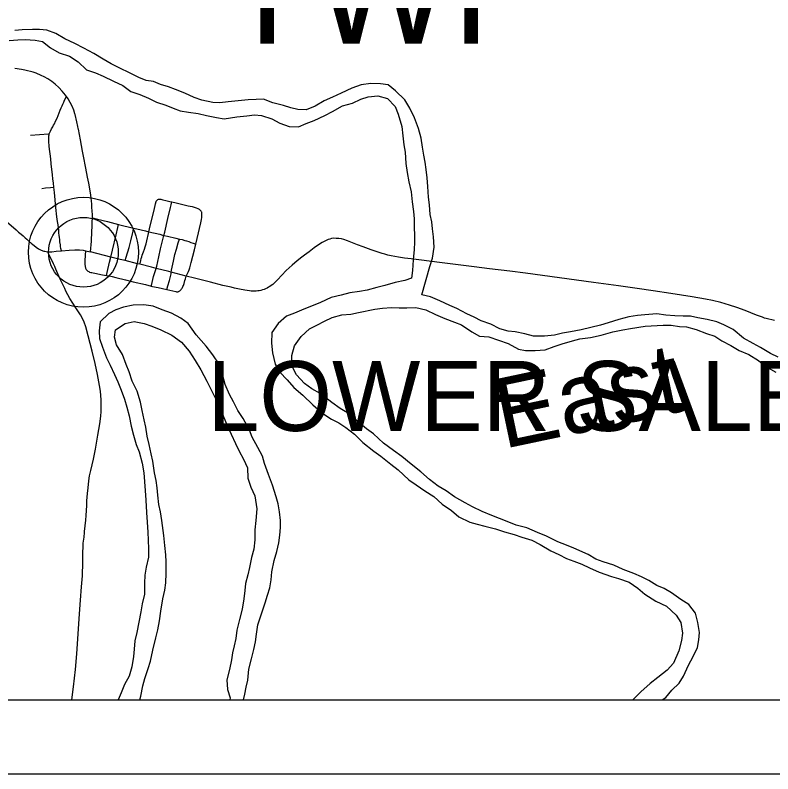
# Model space of a CAD drawing. Extents: x 0 to 34, y 0 to 22.
# Drawn here: x 3.105 to 4.132, y 14 to 15.027 of the extents above; entities that cross this region are included whole.
import ezdxf

# ---------------------------------------------------------------- set-up
doc = ezdxf.new("R2010")
doc.units = 0
for name, color, linetype in [('GM_X_Corporation', 7, 'Continuous'), ('GM_X_Corporation_Text', 7, 'Continuous'), ('GM_X_Major_River', 7, 'Continuous'), ('GM_X_Major_River_Text', 7, 'Continuous'), ('GM_X_State_Route', 7, 'Continuous'), ('GM_X_Township_Road', 7, 'Continuous'), ('GM_X_Township_Text', 7, 'Continuous'), ('GM_X_Unincorporated', 7, 'Continuous'), ('GM_X_Unincorporated_Location', 7, 'Continuous'), ('SH_Data', 7, 'Continuous'), ('SH_Text', 7, 'Continuous')]:
    doc.layers.add(name, color=color, linetype=linetype)

msp = doc.modelspace()

# ---------------------------------------------------------------- linework, layer by layer
at = {"layer": 'GM_X_Corporation'}
msp.add_lwpolyline([(2.1, 19.4241), (2.1, 14.1), (8.9, 14.1), (8.9, 16.8499)], dxfattribs=at)
at = {"layer": 'GM_X_Major_River'}
for points in [[(3.6559, 14.6484), (3.6671, 14.6869), (3.6704, 14.6983), (3.6728, 14.7128), (3.6719, 14.7272), (3.6706, 14.7378), (3.6697, 14.7473), (3.6673, 14.7571), (3.6664, 14.7704), (3.6651, 14.7806), (3.6641, 14.795), (3.6632, 14.8071), (3.6619, 14.8181), (3.6607, 14.828), (3.659, 14.8378), (3.657, 14.8484), (3.6553, 14.8605), (3.6517, 14.8737), (3.6462, 14.8881), (3.64, 14.9013), (3.633, 14.9126), (3.6203, 14.9249), (3.6104, 14.9328), (3.6001, 14.9341), (3.5872, 14.9347), (3.5739, 14.933), (3.5611, 14.9283), (3.5468, 14.9216), (3.5351, 14.9162), (3.5238, 14.9111), (3.5118, 14.9041), (3.4993, 14.899), (3.4883, 14.8992), (3.4785, 14.9017), (3.4689, 14.9047), (3.4545, 14.9086), (3.4415, 14.9134), (3.4317, 14.9129), (3.4211, 14.9127), (3.4074, 14.911), (3.3938, 14.9097), (3.3824, 14.9084), (3.373, 14.909), (3.3581, 14.9119), (3.3478, 14.9155), (3.3353, 14.9214), (3.3223, 14.9266), (3.3128, 14.9302), (3.3021, 14.9331), (3.2926, 14.9372), (3.2827, 14.9386), (3.2728, 14.9426), (3.2594, 14.9496), (3.248, 14.9548), (3.2354, 14.9611), (3.2247, 14.9674), (3.2117, 14.9752), (3.1983, 14.9826), (3.1861, 14.9888), (3.1724, 14.9951), (3.1605, 15.0025), (3.1483, 15.0069), (3.1385, 15.0076), (3.1286, 15.0078), (3.115, 15.0072), (3.1047, 15.0063)], [(3.097, 14.993), (3.1091, 14.9939), (3.1189, 14.9944), (3.1322, 14.9931), (3.1425, 14.9913), (3.1532, 14.9831), (3.1651, 14.976), (3.1788, 14.9717), (3.1906, 14.9639), (3.2021, 14.953), (3.2143, 14.949), (3.2246, 14.9446), (3.2384, 14.9376), (3.2513, 14.9317), (3.2621, 14.9239), (3.2742, 14.9199), (3.2861, 14.9147), (3.2967, 14.9095), (3.3093, 14.9055), (3.3192, 14.9011), (3.3287, 14.8978), (3.3402, 14.8957), (3.3531, 14.894), (3.3645, 14.8915), (3.3778, 14.8886), (3.3884, 14.8869), (3.4054, 14.8894), (3.4191, 14.8907), (3.4293, 14.892), (3.4388, 14.8913), (3.4529, 14.8866), (3.4636, 14.8811), (3.4765, 14.8763), (3.489, 14.8761), (3.4996, 14.8804), (3.5105, 14.8847), (3.5248, 14.8914), (3.535, 14.8968), (3.5486, 14.9042), (3.5622, 14.9082), (3.5735, 14.9133), (3.5833, 14.9164), (3.5965, 14.9178), (3.6095, 14.9141), (3.6202, 14.9033), (3.6242, 14.8931), (3.6289, 14.8765), (3.6306, 14.8636), (3.6319, 14.8515), (3.6336, 14.8416), (3.6345, 14.8261), (3.6362, 14.8143), (3.6387, 14.8015), (3.6419, 14.7879), (3.6432, 14.7742), (3.6449, 14.7613), (3.6458, 14.7515), (3.6456, 14.739), (3.6461, 14.7295), (3.6462, 14.72), (3.6456, 14.7097), (3.6446, 14.6957), (3.6437, 14.6813), (3.6423, 14.671), (3.6329, 14.6678)], [(3.6329, 14.6678), (3.62, 14.665), (3.6061, 14.661), (3.5951, 14.6586), (3.5819, 14.6546), (3.5717, 14.653), (3.5584, 14.6513), (3.5467, 14.6481), (3.5335, 14.6449), (3.5188, 14.6382), (3.5067, 14.6331), (3.4965, 14.6292), (3.4837, 14.6237), (3.4728, 14.6194), (3.4615, 14.6097)], [(3.8719, 14.6012), (3.8575, 14.5984), (3.8465, 14.5964), (3.8359, 14.5939), (3.8223, 14.5926), (3.8072, 14.5924), (3.7957, 14.5957), (3.7824, 14.5985), (3.7729, 14.5995), (3.7619, 14.6024), (3.7497, 14.6087), (3.7364, 14.6135), (3.7268, 14.6183), (3.7169, 14.6227), (3.7035, 14.6301), (3.694, 14.6341), (3.6806, 14.6404), (3.6677, 14.6459), (3.6559, 14.6484)], [(3.4146, 14.1), (3.4164, 14.1079), (3.4181, 14.1174), (3.4203, 14.1269), (3.422, 14.1418), (3.4252, 14.1558), (3.4284, 14.1684), (3.431, 14.1787), (3.4323, 14.189), (3.4341, 14.2015), (3.4384, 14.2152), (3.4439, 14.2316), (3.4472, 14.2419), (3.4501, 14.2518), (3.4522, 14.2624), (3.4528, 14.2735), (3.456, 14.2887), (3.4596, 14.3009), (3.4625, 14.3127), (3.4639, 14.3229), (3.4649, 14.3336), (3.4648, 14.3431), (3.4635, 14.3548), (3.4614, 14.3654), (3.459, 14.3752), (3.4539, 14.3907), (3.4484, 14.4051), (3.4432, 14.4202), (3.4401, 14.43), (3.4339, 14.442), (3.4265, 14.4556), (3.4225, 14.4654), (3.414, 14.4809), (3.407, 14.4921), (3.4012, 14.5034), (3.3954, 14.5136), (3.3899, 14.5272), (3.3859, 14.5423), (3.3815, 14.5544), (3.373, 14.5672), (3.3641, 14.5792), (3.3507, 14.5942), (3.3395, 14.6096), (3.3295, 14.6167), (3.3169, 14.6237), (3.3043, 14.6281), (3.2921, 14.6333), (3.2796, 14.635), (3.2652, 14.6344), (3.252, 14.6316), (3.2418, 14.6284), (3.232, 14.623), (3.2204, 14.6118), (3.219, 14.5996), (3.2196, 14.5894), (3.2235, 14.5777), (3.229, 14.563), (3.2341, 14.5532), (3.2399, 14.5404), (3.2442, 14.5305), (3.2489, 14.5196), (3.2533, 14.5071), (3.2565, 14.4962), (3.2596, 14.4845), (3.2625, 14.4705), (3.2657, 14.4587), (3.2693, 14.4459), (3.2732, 14.4357), (3.2772, 14.4206), (3.2796, 14.4077), (3.2815, 14.3835), (3.2824, 14.3706), (3.2834, 14.3539), (3.2843, 14.3406), (3.2849, 14.3273), (3.2854, 14.3164), (3.286, 14.3046), (3.2857, 14.2932)], [(3.9815, 14.1), (3.9866, 14.1035), (3.9948, 14.1134), (4.0046, 14.1227), (4.0105, 14.1322), (4.0175, 14.1471), (4.0238, 14.1586), (4.0297, 14.1712), (4.0311, 14.1815), (4.0321, 14.1913), (4.03, 14.205), (4.0268, 14.2175), (4.0179, 14.2291), (4.0068, 14.2358), (3.9942, 14.2451), (3.9843, 14.2507), (3.9743, 14.2551), (3.9636, 14.2618), (3.9537, 14.2666), (3.9434, 14.271), (3.9289, 14.2768), (3.916, 14.2824), (3.9015, 14.2871), (3.8916, 14.2908), (3.8813, 14.2967), (3.8622, 14.3055), (3.8519, 14.3096), (3.8401, 14.314), (3.8248, 14.3217), (3.8126, 14.3265), (3.7985, 14.3328), (3.7841, 14.3367), (3.7719, 14.3415), (3.7612, 14.3455), (3.7509, 14.3499), (3.7379, 14.3551), (3.7246, 14.3614), (3.7147, 14.3669), (3.7005, 14.3751), (3.689, 14.3833), (3.6783, 14.3896), (3.6665, 14.3985), (3.6546, 14.409), (3.6419, 14.419), (3.6289, 14.4295), (3.6178, 14.4377), (3.6044, 14.4478), (3.5906, 14.4601), (3.581, 14.4672), (3.5706, 14.4758), (3.5599, 14.4862), (3.5457, 14.4944), (3.5343, 14.5026), (3.5182, 14.5149), (3.5071, 14.5212), (3.4971, 14.5286), (3.4864, 14.5403), (3.4801, 14.5523), (3.4799, 14.5664), (3.4836, 14.5793), (3.4929, 14.592), (3.5041, 14.6023), (3.5139, 14.6074), (3.5241, 14.6129), (3.5346, 14.6176), (3.5478, 14.6212), (3.5599, 14.6225), (3.5705, 14.6245), (3.5924, 14.6293), (3.6027, 14.6306), (3.6152, 14.6315), (3.6254, 14.6309), (3.6357, 14.6307), (3.6478, 14.6312), (3.6615, 14.628), (3.6748, 14.6217), (3.6874, 14.6166), (3.7004, 14.6115), (3.7099, 14.6078), (3.7237, 14.5985), (3.7344, 14.5926), (3.7469, 14.5916), (3.7598, 14.5872), (3.7732, 14.5825), (3.7869, 14.5747), (3.7964, 14.5733), (3.8097, 14.5731), (3.8233, 14.574), (3.8354, 14.5787), (3.846, 14.5823), (3.8603, 14.5863), (3.8701, 14.5887), (3.8845, 14.5908), (3.8989, 14.594), (3.9147, 14.5984), (3.9284, 14.6009), (3.9389, 14.6029)], [(4.1389, 14.5639), (4.1282, 14.569), (4.1148, 14.5772), (4.1049, 14.5828), (4.0919, 14.5898), (4.0777, 14.6014), (4.0651, 14.608), (4.0556, 14.6121), (4.0427, 14.6153), (4.0301, 14.6174), (4.0202, 14.6196), (4.01, 14.6198), (3.999, 14.62), (3.9865, 14.621), (3.9743, 14.6227), (3.958, 14.6214), (3.9482, 14.6205), (3.9365, 14.6188), (3.9229, 14.6152), (3.9085, 14.6105), (3.8979, 14.6073), (3.8851, 14.6041), (3.8719, 14.6012)], [(3.2742, 14.1), (3.2754, 14.1053), (3.2782, 14.1193), (3.2811, 14.1289), (3.2855, 14.1426), (3.2888, 14.1525), (3.2916, 14.1673), (3.2959, 14.1841), (3.2984, 14.1947), (3.3009, 14.2073), (3.3026, 14.2202), (3.3054, 14.2369), (3.3079, 14.2484), (3.3093, 14.2586), (3.3099, 14.2715), (3.3097, 14.2871), (3.3092, 14.2966), (3.3079, 14.3091), (3.3066, 14.3227), (3.304, 14.3428), (3.3023, 14.3545), (3.2999, 14.3647), (3.2986, 14.3772), (3.2977, 14.3871), (3.2961, 14.3969), (3.294, 14.4075), (3.2916, 14.4231), (3.2895, 14.4333), (3.2867, 14.4457), (3.2843, 14.4571), (3.2822, 14.4692), (3.2802, 14.4791), (3.2774, 14.4919), (3.2749, 14.5033), (3.2706, 14.518), (3.2639, 14.5316), (3.2596, 14.5444), (3.2557, 14.5542), (3.2509, 14.5678), (3.2424, 14.581), (3.24, 14.5912), (3.2414, 14.6011), (3.2542, 14.6096), (3.2666, 14.6124), (3.2799, 14.6096), (3.2906, 14.6059), (3.3028, 14.6011), (3.3173, 14.5938), (3.3307, 14.5845), (3.3411, 14.5721), (3.3489, 14.5597), (3.3566, 14.5469)], [(3.4615, 14.6097), (3.453, 14.5975), (3.4524, 14.5831), (3.4537, 14.5698), (3.4577, 14.5547), (3.4636, 14.5437), (3.4736, 14.5333), (3.4828, 14.5228), (3.4951, 14.5127), (3.5085, 14.4996), (3.5219, 14.4876), (3.5338, 14.4802), (3.5437, 14.475), (3.5533, 14.4687), (3.5648, 14.4597), (3.5763, 14.4485), (3.5909, 14.437), (3.6008, 14.4299), (3.6142, 14.4194), (3.6242, 14.4116), (3.6384, 14.3981), (3.6484, 14.3914), (3.6602, 14.3833), (3.6725, 14.3754), (3.6836, 14.365), (3.6962, 14.3564), (3.7062, 14.3478), (3.7211, 14.3408), (3.731, 14.3379), (3.7416, 14.3354), (3.7557, 14.3318), (3.7683, 14.3278), (3.7812, 14.3242), (3.7915, 14.3205), (3.8052, 14.3162), (3.8166, 14.3106), (3.8308, 14.3021), (3.8415, 14.2969), (3.8522, 14.2914), (3.8621, 14.2877), (3.8727, 14.2837), (3.883, 14.2789), (3.8964, 14.273), (3.9128, 14.2671), (3.9223, 14.2646), (3.9371, 14.2595), (3.9486, 14.2513), (3.9582, 14.2431), (3.9731, 14.2338), (3.9876, 14.2268), (4.0007, 14.2148), (4.0069, 14.205), (4.0093, 14.1903), (4.0076, 14.1804), (4.0044, 14.1663), (3.997, 14.1499), (3.9884, 14.1403), (3.9756, 14.1306), (3.9655, 14.1222), (3.9528, 14.111), (3.9418, 14.1)], [(3.9389, 14.6029), (3.9586, 14.6062), (3.9829, 14.6073), (3.9939, 14.6075), (4.0053, 14.6057), (4.0147, 14.6051), (4.0277, 14.6015), (4.0418, 14.5963), (4.0528, 14.5923), (4.0624, 14.586), (4.0746, 14.5797), (4.0861, 14.573), (4.099, 14.5675), (4.112, 14.5597), (4.122, 14.5515), (4.1357, 14.5437)], [(3.3566, 14.5469), (3.3648, 14.5314), (3.373, 14.5152), (3.3796, 14.5016), (3.3851, 14.4892), (3.3909, 14.4749), (3.398, 14.4598), (3.4038, 14.4473), (3.4089, 14.4368), (3.4147, 14.4258), (3.4198, 14.4142), (3.4204, 14.4001), (3.4247, 14.388), (3.4298, 14.3763), (3.4327, 14.3589), (3.4314, 14.343), (3.4301, 14.3301), (3.4299, 14.3168), (3.4285, 14.3042), (3.4256, 14.2928), (3.4228, 14.2795), (3.4206, 14.2692), (3.4174, 14.2578), (3.4164, 14.2483), (3.415, 14.2369), (3.4129, 14.2228), (3.4093, 14.2091), (3.4057, 14.1943), (3.4044, 14.1833), (3.4018, 14.1734), (3.3997, 14.1639), (3.3983, 14.1543), (3.3955, 14.141), (3.3922, 14.1273), (3.3928, 14.1141), (3.3964, 14.1027), (3.3959, 14.1)], [(3.2857, 14.2932), (3.2829, 14.2799), (3.2811, 14.2689), (3.2805, 14.2579), (3.2803, 14.2434), (3.2775, 14.2301), (3.2757, 14.2191), (3.2729, 14.2054), (3.27, 14.1913), (3.2675, 14.1799), (3.2666, 14.1689), (3.2656, 14.1586), (3.2635, 14.1446), (3.2599, 14.132), (3.2536, 14.1209), (3.2488, 14.1095), (3.2448, 14.1)]]:
    msp.add_lwpolyline(points, dxfattribs=at)
at = {"layer": 'GM_X_State_Route'}
for points in [[(3.1748, 14.917), (3.1734, 14.9189), (3.1691, 14.9242), (3.1644, 14.9293), (3.1597, 14.9335), (3.1548, 14.9374), (3.1495, 14.9408), (3.1446, 14.9436), (3.1407, 14.9455), (3.1337, 14.9484), (3.1295, 14.9498), (3.1186, 14.9526), (3.1137, 14.9534), (3.1051, 14.9548)], [(3.1862, 14.8936), (3.1846, 14.8986), (3.1824, 14.9038), (3.1799, 14.9089), (3.177, 14.9137), (3.1748, 14.917)], [(3.1908, 14.8737), (3.1904, 14.8763), (3.189, 14.8829), (3.1865, 14.8926), (3.1862, 14.8936)], [(3.2098, 14.7469), (3.2099, 14.7529), (3.2099, 14.7574), (3.2097, 14.7617), (3.2093, 14.7673), (3.2091, 14.771), (3.2087, 14.776), (3.2083, 14.779), (3.2076, 14.7839), (3.2049, 14.7998), (3.2033, 14.8077), (3.201, 14.8199), (3.1979, 14.8363), (3.1967, 14.8431), (3.1938, 14.8583), (3.1909, 14.8728), (3.1908, 14.8737)], [(3.0938, 14.7478), (3.1068, 14.7364), (3.11, 14.7335), (3.1133, 14.7306), (3.116, 14.7282), (3.1188, 14.7257), (3.1211, 14.7237), (3.123, 14.722), (3.1248, 14.7204), (3.1262, 14.7192), (3.1276, 14.7181), (3.129, 14.7169), (3.1337, 14.7129), (3.1369, 14.7108), (3.1397, 14.7093), (3.1426, 14.7082), (3.1443, 14.7077), (3.1455, 14.7074), (3.1473, 14.707), (3.1496, 14.7066), (3.1506, 14.7065), (3.1528, 14.7065), (3.155, 14.7067), (3.1609, 14.7074), (3.1673, 14.708), (3.1679, 14.708), (3.1783, 14.709), (3.1863, 14.7094), (3.1925, 14.7094), (3.1973, 14.7089), (3.2008, 14.7082), (3.2074, 14.7069)], [(3.2074, 14.7069), (3.2085, 14.7213), (3.2087, 14.725), (3.2091, 14.73), (3.2098, 14.7449), (3.2098, 14.7469)], [(4.134, 14.6137), (4.1303, 14.6145), (4.1261, 14.6156), (4.1226, 14.6166), (4.1204, 14.6171), (4.1177, 14.6181), (4.1135, 14.6196), (4.1095, 14.621), (4.0939, 14.6271), (4.0828, 14.6312), (4.0729, 14.6346), (4.061, 14.6381), (4.0496, 14.6409), (4.0405, 14.6427), (4.0221, 14.6458), (3.9933, 14.6502), (3.9693, 14.6539), (3.9478, 14.6572), (3.9225, 14.6608), (3.8887, 14.6654), (3.7964, 14.6777), (3.7754, 14.6804), (3.7478, 14.6839), (3.7268, 14.6866), (3.68, 14.6924), (3.6418, 14.6972), (3.6327, 14.6983), (3.6245, 14.6995), (3.6194, 14.7003), (3.6147, 14.7014), (3.61, 14.7024), (3.6062, 14.7034), (3.6025, 14.7045), (3.5984, 14.7056), (3.5929, 14.7074), (3.5877, 14.7092), (3.5767, 14.7134), (3.5692, 14.7164), (3.5553, 14.7217), (3.5506, 14.7232), (3.5471, 14.7241), (3.5437, 14.7247), (3.5399, 14.7249), (3.5371, 14.725), (3.5339, 14.7246), (3.5315, 14.724), (3.5292, 14.7233), (3.5264, 14.7222), (3.5238, 14.7209), (3.521, 14.7194), (3.5174, 14.7171), (3.5105, 14.712), (3.506, 14.7086), (3.5035, 14.7068), (3.4974, 14.7022), (3.4936, 14.6993), (3.4873, 14.6944), (3.4804, 14.6886), (3.4726, 14.6813), (3.4607, 14.6686), (3.4562, 14.6643), (3.4542, 14.6626), (3.4522, 14.6611), (3.4503, 14.6598), (3.4485, 14.6587), (3.4465, 14.6576), (3.4445, 14.6567), (3.4424, 14.6558), (3.4403, 14.6551), (3.4381, 14.6545), (3.436, 14.6541), (3.4339, 14.6538), (3.4316, 14.6535), (3.4297, 14.6534), (3.4278, 14.6534), (3.4251, 14.6536), (3.4227, 14.6538), (3.4196, 14.6542), (3.4165, 14.6547), (3.4091, 14.6561), (3.4025, 14.6576), (3.3979, 14.6587)], [(3.3371, 14.6739), (3.3168, 14.6791), (3.3134, 14.68), (3.2965, 14.6843), (3.2899, 14.686), (3.2741, 14.6899), (3.2712, 14.6906), (3.2542, 14.6948), (3.2477, 14.6964), (3.235, 14.6997), (3.2074, 14.7069)], [(3.3979, 14.6587), (3.3868, 14.6613), (3.37, 14.6655), (3.3483, 14.671), (3.3371, 14.6739)]]:
    msp.add_lwpolyline(points, dxfattribs=at)
at = {"layer": 'GM_X_Township_Road'}
for points in [[(3.159, 14.8813), (3.1596, 14.8824), (3.1606, 14.8846), (3.1621, 14.8875), (3.1637, 14.8913), (3.1651, 14.8947), (3.1665, 14.8985), (3.1678, 14.9016), (3.1689, 14.9044), (3.1699, 14.9068), (3.1711, 14.9093), (3.1723, 14.9119), (3.1748, 14.917)], [(3.1516, 14.8666), (3.1519, 14.8674), (3.1523, 14.8681), (3.1527, 14.8691), (3.1531, 14.8699), (3.1547, 14.8732), (3.1562, 14.8759), (3.1573, 14.878), (3.1585, 14.8802), (3.159, 14.8813)], [(3.126, 14.8647), (3.1506, 14.8666), (3.1516, 14.8666)], [(3.1578, 14.7944), (3.1572, 14.7995), (3.1565, 14.8055), (3.1557, 14.811), (3.1543, 14.8258), (3.1536, 14.8325), (3.1514, 14.8491), (3.1512, 14.8514), (3.151, 14.8545), (3.1508, 14.8582), (3.1508, 14.86), (3.1508, 14.8618), (3.1509, 14.8627), (3.151, 14.8636), (3.1512, 14.8649), (3.1514, 14.8657), (3.1516, 14.8666)], [(3.1414, 14.7926), (3.1464, 14.7932), (3.1533, 14.794), (3.1578, 14.7944)], [(3.1679, 14.708), (3.1674, 14.7112), (3.1669, 14.7141), (3.1666, 14.7164), (3.166, 14.7203), (3.1656, 14.7232), (3.1653, 14.7263), (3.1649, 14.7291), (3.1646, 14.7319), (3.1643, 14.7354), (3.1634, 14.7431), (3.1628, 14.7479), (3.1619, 14.7541), (3.1605, 14.7666), (3.1585, 14.7872), (3.1578, 14.7944)], [(3.2865, 14.734), (3.2884, 14.7419), (3.2921, 14.7579), (3.2939, 14.7655), (3.2949, 14.7695), (3.2955, 14.7719), (3.2962, 14.7747), (3.2964, 14.7753), (3.297, 14.7762), (3.2975, 14.7767), (3.2986, 14.7776)], [(3.2986, 14.7776), (3.2995, 14.778), (3.3003, 14.7781), (3.3014, 14.7781), (3.3024, 14.7779), (3.3041, 14.7775), (3.3055, 14.7771), (3.3095, 14.7761), (3.3167, 14.7744), (3.3177, 14.7742)], [(3.3069, 14.7289), (3.308, 14.7332), (3.3123, 14.752), (3.3157, 14.7666), (3.3166, 14.7702), (3.3177, 14.7742)], [(3.3177, 14.7742), (3.3232, 14.7729), (3.3306, 14.7711), (3.3395, 14.7691), (3.3452, 14.7679), (3.3506, 14.7664), (3.3528, 14.7654), (3.3545, 14.7645), (3.3559, 14.7633), (3.3571, 14.7619)], [(3.3499, 14.717), (3.3503, 14.7189), (3.3551, 14.7382), (3.3569, 14.7461), (3.3577, 14.7504), (3.358, 14.7534), (3.3582, 14.7553), (3.3583, 14.7571), (3.3583, 14.7583), (3.3582, 14.7594), (3.358, 14.7602), (3.3577, 14.7608), (3.3571, 14.7619)], [(3.2099, 14.7529), (3.2167, 14.7511), (3.2305, 14.7476), (3.2454, 14.7439)], [(3.235, 14.6997), (3.2373, 14.709), (3.2419, 14.7295), (3.2444, 14.7397), (3.2454, 14.7439)], [(3.2454, 14.7439), (3.2473, 14.7434), (3.2636, 14.7393), (3.2658, 14.7388)], [(3.2542, 14.6948), (3.2557, 14.6995), (3.2598, 14.7126), (3.2622, 14.7216), (3.2643, 14.7313), (3.265, 14.7348), (3.2658, 14.7388)], [(3.2658, 14.7388), (3.2702, 14.7377), (3.2817, 14.7351), (3.2865, 14.734)], [(3.2741, 14.6899), (3.2743, 14.6907), (3.2749, 14.6927), (3.2755, 14.695), (3.2762, 14.6975), (3.2768, 14.6998), (3.2775, 14.7021), (3.2783, 14.7044), (3.2791, 14.7068), (3.2803, 14.7103), (3.2815, 14.7137), (3.2827, 14.7175), (3.2837, 14.7215), (3.286, 14.7315), (3.2865, 14.734)], [(3.2865, 14.734), (3.3014, 14.7304), (3.3049, 14.7294), (3.3069, 14.7289)], [(3.2965, 14.6843), (3.2971, 14.6873), (3.2999, 14.7001), (3.3023, 14.7106), (3.3049, 14.7215), (3.3069, 14.7289)], [(3.3069, 14.7289), (3.3115, 14.7278), (3.3229, 14.7251), (3.3279, 14.724)], [(3.3168, 14.6791), (3.3172, 14.6819), (3.3197, 14.6941), (3.3218, 14.7032), (3.3238, 14.7104), (3.3263, 14.7188), (3.3279, 14.724)], [(3.3279, 14.724), (3.3314, 14.7232), (3.3352, 14.7222), (3.3376, 14.7215), (3.3405, 14.7206), (3.3434, 14.7195), (3.3463, 14.7184), (3.3499, 14.717)], [(3.3371, 14.6739), (3.3379, 14.6756), (3.3387, 14.6775), (3.3399, 14.6803), (3.3408, 14.6822), (3.3413, 14.6836), (3.3418, 14.6851), (3.3438, 14.6923), (3.348, 14.7092), (3.3499, 14.717)], [(3.1823, 14.1), (3.1843, 14.1177), (3.1871, 14.1411), (3.1888, 14.1622), (3.1926, 14.2167), (3.1938, 14.2353), (3.1952, 14.2532), (3.1963, 14.2681), (3.1969, 14.2867), (3.1968, 14.2884), (3.1969, 14.2919), (3.1971, 14.3004), (3.1973, 14.3065), (3.1975, 14.3102), (3.1976, 14.3121), (3.1987, 14.3206), (3.1993, 14.3268), (3.1994, 14.328), (3.2011, 14.3434), (3.2016, 14.3496), (3.2022, 14.3632), (3.2024, 14.3694), (3.2031, 14.3793), (3.204, 14.3873), (3.2052, 14.3965), (3.2062, 14.4032), (3.2077, 14.4105), (3.2113, 14.4262), (3.2141, 14.4396), (3.2175, 14.4586), (3.22, 14.4739), (3.2213, 14.4844), (3.2218, 14.4906), (3.222, 14.4974), (3.2218, 14.5061), (3.2214, 14.5123), (3.2208, 14.5179), (3.2196, 14.5258), (3.2168, 14.5405), (3.2136, 14.5557), (3.2097, 14.572), (3.2044, 14.5931), (3.2009, 14.605), (3.1987, 14.6115), (3.1964, 14.6166), (3.1937, 14.6214), (3.1893, 14.6282), (3.1865, 14.6324), (3.1835, 14.637), (3.1795, 14.6433), (3.1765, 14.6487), (3.1739, 14.6536), (3.1724, 14.657), (3.1663, 14.6699), (3.1605, 14.6834), (3.1595, 14.6855), (3.1592, 14.6867), (3.1588, 14.6876), (3.1574, 14.6904), (3.1564, 14.6925), (3.1537, 14.6978), (3.1506, 14.7045), (3.1496, 14.7066)], [(3.2008, 14.7082), (3.2003, 14.7024), (3.1996, 14.6943), (3.1996, 14.6899), (3.2, 14.6868), (3.2007, 14.6845), (3.2015, 14.6828), (3.2027, 14.6813), (3.2037, 14.6805), (3.2049, 14.6799), (3.2061, 14.6794), (3.2076, 14.6788), (3.209, 14.6785), (3.211, 14.6781), (3.2134, 14.6776), (3.2238, 14.6757), (3.2289, 14.6748)], [(3.2289, 14.6748), (3.2298, 14.6785), (3.2333, 14.6928), (3.235, 14.6997)], [(3.2897, 14.6604), (3.2899, 14.6613), (3.2929, 14.6731), (3.2965, 14.6843)], [(3.3107, 14.6556), (3.3122, 14.6607), (3.3144, 14.6678), (3.3154, 14.6715), (3.3162, 14.6749), (3.3165, 14.6769), (3.3168, 14.6791)], [(3.2289, 14.6748), (3.2328, 14.674), (3.2369, 14.6731), (3.2415, 14.6721), (3.2547, 14.6688), (3.265, 14.6663), (3.2819, 14.6623), (3.2897, 14.6604)], [(3.3107, 14.6556), (3.3228, 14.6528), (3.324, 14.6526), (3.3249, 14.6526), (3.3259, 14.6526), (3.3267, 14.653), (3.3273, 14.6533), (3.3282, 14.6539), (3.3292, 14.6547), (3.33, 14.6556), (3.3306, 14.6564), (3.3314, 14.6575), (3.3319, 14.6584), (3.3325, 14.6597), (3.3331, 14.6612), (3.3341, 14.6638), (3.3352, 14.6677), (3.336, 14.6702), (3.3371, 14.6739)], [(3.2897, 14.6604), (3.2915, 14.6599), (3.2988, 14.6582), (3.3107, 14.6556)]]:
    msp.add_lwpolyline(points, dxfattribs=at)
at = {"layer": 'GM_X_Unincorporated'}
for radius in [0.0744, 0.0472]:
    msp.add_circle((3.1978, 14.7061), radius, dxfattribs=at)
at = {"layer": 'GM_X_Unincorporated_Location'}
msp.add_line((3.1978, 14.7061), (3.1978, 14.7061), dxfattribs=at)
at = {"layer": 'SH_Data'}
for p, q in [((2.1, 14.1), (8.9, 14.1)), ((2, 14), (9, 14))]:
    msp.add_line(p, q, dxfattribs=at)
at = {"layer": 'SH_Text'}
msp.add_lwpolyline([(2.1, 16.074), (2.1, 14.1), (6.4323, 14.1)], dxfattribs=at)

# ---------------------------------------------------------------- texts
at = {"layer": 'GM_X_Corporation_Text'}
msp.add_text('LOWER SALEM', height=0.094697, rotation=0, dxfattribs=at).set_placement((3.3656, 14.4642))
at = {"layer": 'GM_X_Major_River_Text'}
msp.add_text('East', height=0.0947, rotation=11.9052, dxfattribs=at).set_placement((3.7664, 14.4397))
at = {"layer": 'GM_X_Township_Text'}
msp.add_text('TWP', height=0.15, rotation=0, dxfattribs=at).set_placement((3.3853, 14.9887))

doc.saveas('drawing.dxf')
